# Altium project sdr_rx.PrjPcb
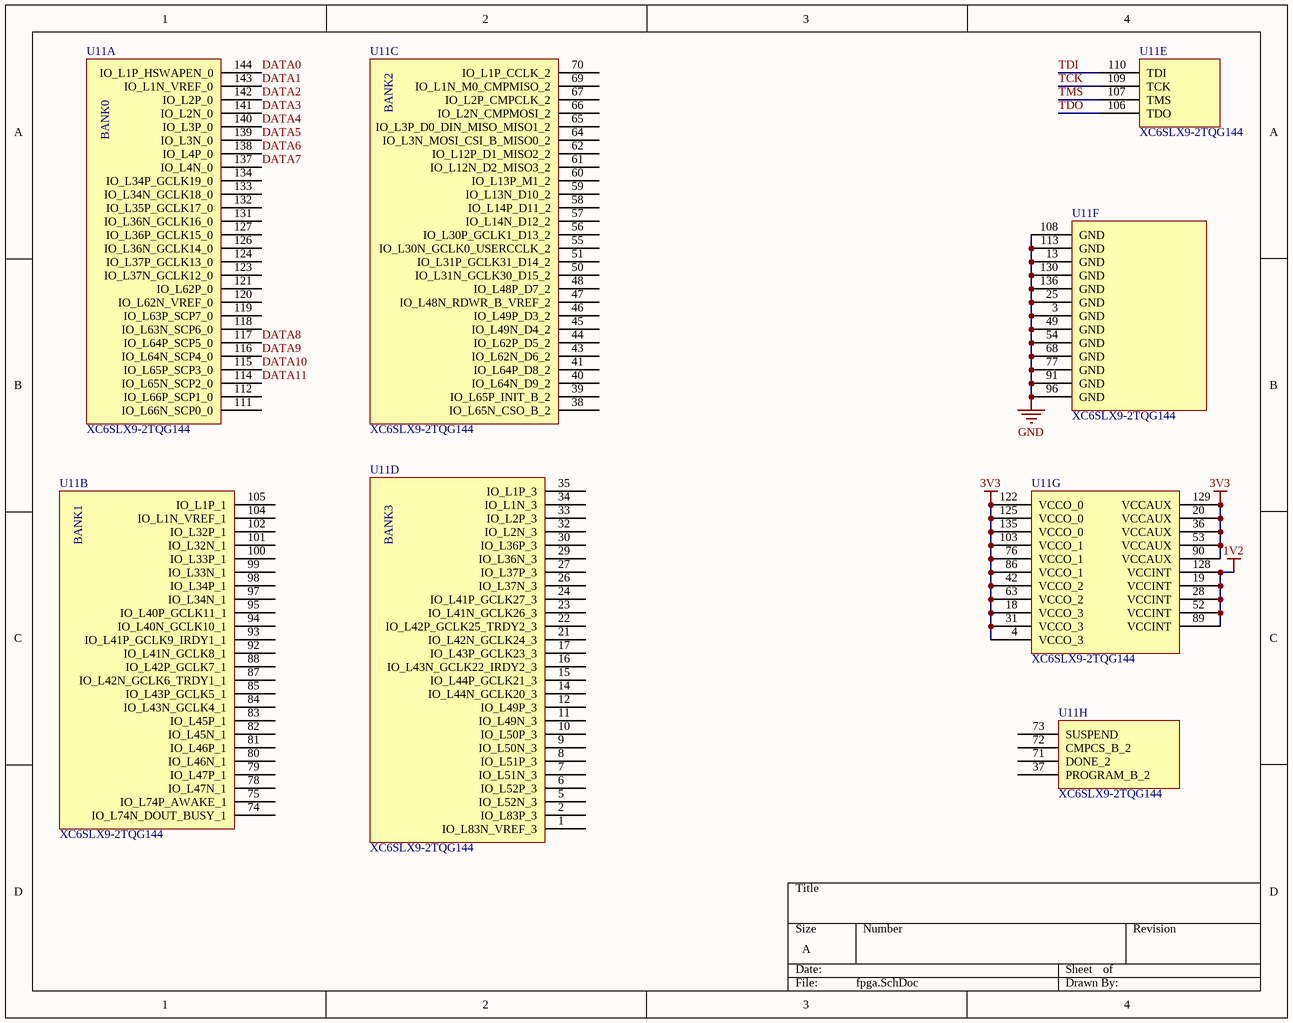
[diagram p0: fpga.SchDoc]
4 sheets, 10 parts. Net scope: global (net labels, ports and power ports of the same name join across sheets).
Board file: sdr_rx.PcbDoc
Sheets:
  fpga.SchDoc
  usbif.SchDoc
  power.SchDoc
  adc.SchDoc

## Sheet fpga.SchDoc
size A

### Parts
U11  XC6SLX9-2TQG144  [TSQFP50P2200X2200X160-144N]  (parts A,B,C,D,E,F,G,H of 8)

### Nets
1V2: U11.19(VCCINT) U11.28(VCCINT) U11.52(VCCINT) U11.89(VCCINT) U11.128(VCCINT)
3V3: U11.4(VCCO_3) U11.18(VCCO_3) U11.20(VCCAUX) U11.31(VCCO_3) U11.36(VCCAUX) U11.42(VCCO_2) U11.53(VCCAUX) U11.63(VCCO_2) U11.76(VCCO_1) U11.86(VCCO_1) U11.90(VCCAUX) U11.103(VCCO_1) U11.122(VCCO_0) U11.125(VCCO_0) U11.129(VCCAUX) U11.135(VCCO_0)
GND: U11.3(GND) U11.13(GND) U11.25(GND) U11.49(GND) U11.54(GND) U11.68(GND) U11.77(GND) U11.91(GND) U11.96(GND) U11.108(GND) U11.113(GND) U11.130(GND) U11.136(GND)
DATA0: U11.144(IO_L1P_HSWAPEN_0)
DATA1: U11.143(IO_L1N_VREF_0)
DATA2: U11.142(IO_L2P_0)
DATA3: U11.141(IO_L2N_0)
DATA4: U11.140(IO_L3P_0)
DATA5: U11.139(IO_L3N_0)
DATA6: U11.138(IO_L4P_0)
DATA7: U11.137(IO_L4N_0)
DATA8: U11.117(IO_L64P_SCP5_0)
DATA9: U11.116(IO_L64N_SCP4_0)
DATA10: U11.115(IO_L65P_SCP3_0)
DATA11: U11.114(IO_L65N_SCP2_0)
TCK: U11.109(TCK)
TDI: U11.110(TDI)
TDO: U11.106(TDO)
TMS: U11.107(TMS)

Not connected (* = marked no-connect by the designer): U11 1(IO_L83N_VREF_3) 2(IO_L83P_3) 5(IO_L52N_3) 6(IO_L52P_3) 7(IO_L51N_3) 8(IO_L51P_3) 9(IO_L50N_3) 10(IO_L50P_3) 11(IO_L49N_3) 12(IO_L49P_3) 14(IO_L44N_GCLK20_3) 15(IO_L44P_GCLK21_3) 16(IO_L43N_GCLK22_IRDY2_3) 17(IO_L43P_GCLK23_3) 21(IO_L42N_GCLK24_3) 22(IO_L42P_GCLK25_TRDY2_3) 23(IO_L41N_GCLK26_3) 24(IO_L41P_GCLK27_3) 26(IO_L37N_3) 27(IO_L37P_3) 29(IO_L36N_3) 30(IO_L36P_3) 32(IO_L2N_3) 33(IO_L2P_3) 34(IO_L1N_3) 35(IO_L1P_3) 37(PROGRAM_B_2) 38(IO_L65N_CSO_B_2) 39(IO_L65P_INIT_B_2) 40(IO_L64N_D9_2) 41(IO_L64P_D8_2) 43(IO_L62N_D6_2) 44(IO_L62P_D5_2) 45(IO_L49N_D4_2) 46(IO_L49P_D3_2) 47(IO_L48N_RDWR_B_VREF_2) 48(IO_L48P_D7_2) 50(IO_L31N_GCLK30_D15_2) 51(IO_L31P_GCLK31_D14_2) 55(IO_L30N_GCLK0_USERCCLK_2) 56(IO_L30P_GCLK1_D13_2) 57(IO_L14N_D12_2) 58(IO_L14P_D11_2) 59(IO_L13N_D10_2) 60(IO_L13P_M1_2) 61(IO_L12N_D2_MISO3_2) 62(IO_L12P_D1_MISO2_2) 64(IO_L3N_MOSI_CSI_B_MISO0_2) 65(IO_L3P_D0_DIN_MISO_MISO1_2) 66(IO_L2N_CMPMOSI_2) 67(IO_L2P_CMPCLK_2) 69(IO_L1N_M0_CMPMISO_2) 70(IO_L1P_CCLK_2) 71(DONE_2) 72(CMPCS_B_2) 73(SUSPEND) 74(IO_L74N_DOUT_BUSY_1) 75(IO_L74P_AWAKE_1) 78(IO_L47N_1) 79(IO_L47P_1) 80(IO_L46N_1) 81(IO_L46P_1) 82(IO_L45N_1) 83(IO_L45P_1) 84(IO_L43N_GCLK4_1) 85(IO_L43P_GCLK5_1) 87(IO_L42N_GCLK6_TRDY1_1) 88(IO_L42P_GCLK7_1) 92(IO_L41N_GCLK8_1) 93(IO_L41P_GCLK9_IRDY1_1) 94(IO_L40N_GCLK10_1) 95(IO_L40P_GCLK11_1) 97(IO_L34N_1) 98(IO_L34P_1) 99(IO_L33N_1) 100(IO_L33P_1) 101(IO_L32N_1) 102(IO_L32P_1) 104(IO_L1N_VREF_1) 105(IO_L1P_1) 111(IO_L66N_SCP0_0) 112(IO_L66P_SCP1_0) 118(IO_L63N_SCP6_0) 119(IO_L63P_SCP7_0) 120(IO_L62N_VREF_0) 121(IO_L62P_0) 123(IO_L37N_GCLK12_0) 124(IO_L37P_GCLK13_0) 126(IO_L36N_GCLK14_0) 127(IO_L36P_GCLK15_0) 131(IO_L36N_GCLK16_0) 132(IO_L35P_GCLK17_0) 133(IO_L34N_GCLK18_0) 134(IO_L34P_GCLK19_0)

## Sheet usbif.SchDoc
size A
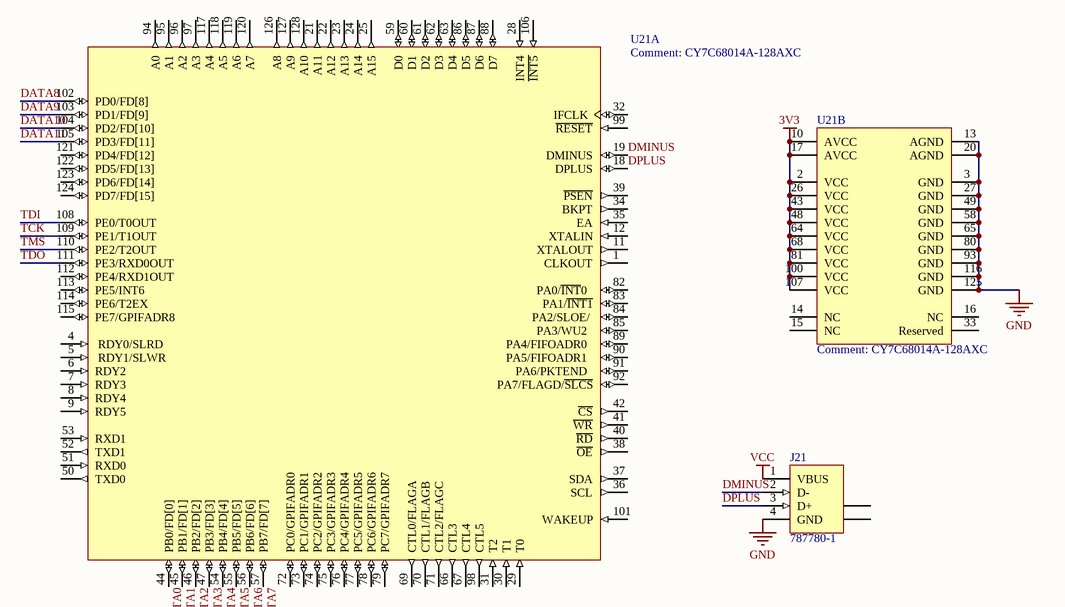
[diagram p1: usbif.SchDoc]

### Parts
J21  787780-1  [787780]
U21  CY7C68014A-128AXC  [A128_N]  (parts A,B of 2)

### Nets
3V3: U21.2(VCC) U21.10(AVCC) U21.17(AVCC) U21.26(VCC) U21.43(VCC) U21.48(VCC) U21.64(VCC) U21.68(VCC) U21.81(VCC) U21.100(VCC) U21.107(VCC)
GND: J21.4(GND) U21.3(GND) U21.13(AGND) U21.20(AGND) U21.27(GND) U21.49(GND) U21.58(GND) U21.65(GND) U21.80(GND) U21.93(GND) U21.116(GND) U21.125(GND)
VCC: J21.1(VBUS)
DATA0: U21.44(PB0/FD[0])
DATA1: U21.45(PB1/FD[1])
DATA2: U21.46(PB2/FD[2])
DATA3: U21.47(PB3/FD[3])
DATA4: U21.54(PB4/FD[4])
DATA5: U21.55(PB5/FD[5])
DATA6: U21.56(PB6/FD[6])
DATA7: U21.57(PB7/FD[7])
DATA8: U21.102(PD0/FD[8])
DATA9: U21.103(PD1/FD[9])
DATA10: U21.104(PD2/FD[10])
DATA11: U21.105(PD3/FD[11])
DMINUS: J21.2(D-) U21.19(DMINUS)
DPLUS: J21.3(D+) U21.18(DPLUS)
TCK: U21.109(PE1/T1OUT)
TDI: U21.108(PE0/T0OUT)
TDO: U21.111(PE3/RXD0OUT)
TMS: U21.110(PE2/T2OUT)

Not connected (* = marked no-connect by the designer): J21 5(SHLD) 6(SHLD); U21 1(CLKOUT) 4(_RDY0/SLRD__) 5(_RDY1/SLWR__) 6(RDY2) 7(RDY3) 8(RDY4) 9(RDY5) 11(XTALOUT) 12(XTALIN) 14(NC) 15(NC) 16(NC) 21(A11) 22(A12) 23(A13) 24(A14) 25(A15) 28(INT4) 29(T0) 30(T1) 31(T2) 32(_IFCLK) 33(Reserved) 34(BKPT) 35(EA) 36(SCL) 37(SDA) 38(~{OE}) 39(~{PSEN}) 40(~{RD}) 41(~{WR}) 42(~{CS}) 50(TXD0) 51(RXD0) 52(TXD1) 53(RXD1) 59(D0) 60(D1) 61(D2) 62(D3) 63(D4) 66(CTL3) 67(CTL4) 69(CTL0/FLAGA__) 70(CTL1/FLAGB__) 71(CTL2/FLAGC__) 72(PC0/GPIFADR0__) 73(PC1/GPIFADR1__) 74(PC2/GPIFADR2__) 75(PC3/GPIFADR3__) 76(PC4/GPIFADR4__) 77(PC5/GPIFADR5__) 78(PC6/GPIFADR6__) 79(PC7/GPIFADR7__) 82(PA0/~{INT}0__) 83(PA1/~{INT1}) 84(PA2/SLOE/_) 85(PA3/WU2__) 86(D5) 87(D6) 88(D7) 89(PA4/FIFOADR0__) 90(PA5/FIFOADR1__) 91(PA6/PKTEND__) 92(PA7/FLAGD/~{SLCS}) 94(A0) 95(A1) 96(A2) 97(A3) 98(CTL5) 99(~{RESET}) 101(WAKEUP) 106(~{INT5}) 112(PE4/RXD1OUT__) 113(PE5/INT6__) 114(PE6/T2EX__) 115(PE7/GPIFADR8__) 117(A4) 118(A5) 119(A6) 120(A7) 121(PD4/FD[12]__) 122(PD5/FD[13]__) 123(PD6/FD[14]__) 124(PD7/FD[15]__) 126(A8) 127(A9) 128(A10)

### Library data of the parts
J21 = 787780-1: USB 1.1, Right Angle, Thru-Hole, B Type, Receptacle, 4 Position, Black; ContactMaterial: Copper Alloy; ContactPlating: Gold Flash over Palladium Nickel or Gold (30) over Nickel; TerminationLength: 3.00mm [0.118in.]; PCB_Layout: Complies with manufacturer's recommendation.; DrillSize: Corresponds to nominal value.; PanelGround: Without
U21 = CY7C68014A-128AXC: EZ-USB FX2LP USB Microcontroller Ideal for Battery Powered Applications,16K RAM, 40 I/Os, 128-Pin TQFP, Pb-Free, Commercial Grade

## Sheet power.SchDoc
size A
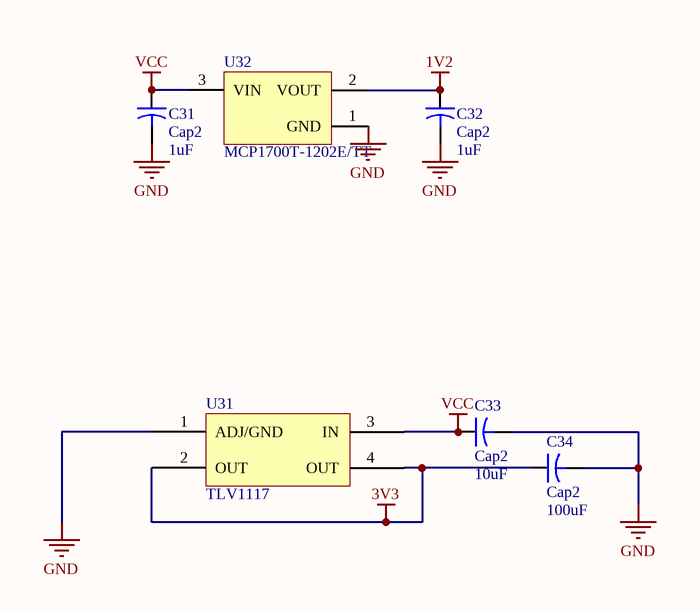
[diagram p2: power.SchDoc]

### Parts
C31  Cap2  value 1uF  [CAPR5-4X5]
C32  Cap2  value 1uF  [CAPR5-4X5]
C33  Cap2  value 10uF  [CAPR5-4X5]
C34  Cap2  value 100uF  [CAPR5-4X5]
U31  TLV1117  [SOT230P700X180-4N]
U32  MCP1700T-1202E/TT  [SOT-23-TT3_N]

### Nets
1V2: C32.1 U32.2(VOUT)
3V3: C34.1 U31.2(OUT) U31.4(OUT)
GND: C31.2 C32.2 C33.2 C34.2 U31.1(ADJ/GND) U32.1(GND)
VCC: C31.1 C33.1 U31.3(IN) U32.3(VIN)

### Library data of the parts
C31-C34 = Cap2: Capacitor
U32 = MCP1700T-1202E/TT: Low Quiescent Current LDO, 3-Pin SOT-23, Extended Temperature, Tape and Reel

## Sheet adc.SchDoc
size A
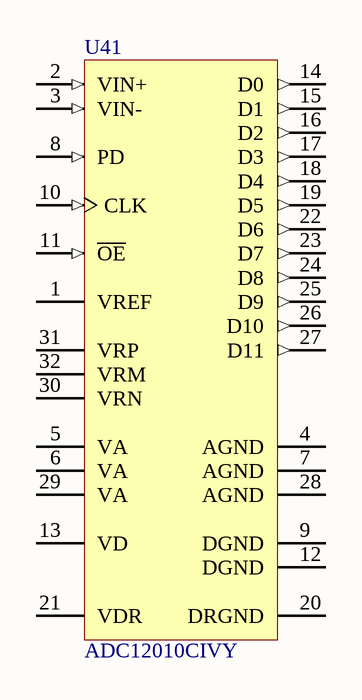
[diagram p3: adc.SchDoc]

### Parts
U41  ADC12010CIVY  [VBE32A_N]

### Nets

Not connected (* = marked no-connect by the designer): U41 1(VREF) 2(VIN+) 3(VIN-) 4(AGND) 5(VA) 6(VA) 7(AGND) 8(PD) 9(DGND) 10(CLK) 11(~{OE}) 12(DGND) 13(VD) 14(D0) 15(D1) 16(D2) 17(D3) 18(D4) 19(D5) 20(DRGND) 21(VDR) 22(D6) 23(D7) 24(D8) 25(D9) 26(D10) 27(D11) 28(AGND) 29(VA) 30(VRN) 31(VRP) 32(VRM)

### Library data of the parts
U41 = ADC12010CIVY: 12-Bit, 10 MSPS, 160 mW A/D Converter with Internal Sample-and-Hold; Manufacturer: National Semiconductor; CompType: ADC IC; PackageTopMarking: NSUZXYTT*ADC12010*CIVY; PowerWise: N

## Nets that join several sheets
1V2: fpga (5 pins), power (C32.1 U32.2)
3V3: fpga (16 pins), usbif (11 pins), power (C34.1 U31.2 U31.4)
GND: fpga (13 pins), usbif (12 pins), power (6 pins)
VCC: usbif (J21.1), power (C31.1 C33.1 U31.3 U32.3)
DATA0: fpga (U11.144), usbif (U21.44)
DATA1: fpga (U11.143), usbif (U21.45)
DATA2: fpga (U11.142), usbif (U21.46)
DATA3: fpga (U11.141), usbif (U21.47)
DATA4: fpga (U11.140), usbif (U21.54)
DATA5: fpga (U11.139), usbif (U21.55)
DATA6: fpga (U11.138), usbif (U21.56)
DATA7: fpga (U11.137), usbif (U21.57)
DATA8: fpga (U11.117), usbif (U21.102)
DATA9: fpga (U11.116), usbif (U21.103)
DATA10: fpga (U11.115), usbif (U21.104)
DATA11: fpga (U11.114), usbif (U21.105)
TCK: fpga (U11.109), usbif (U21.109)
TDI: fpga (U11.110), usbif (U21.108)
TDO: fpga (U11.106), usbif (U21.111)
TMS: fpga (U11.107), usbif (U21.110)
